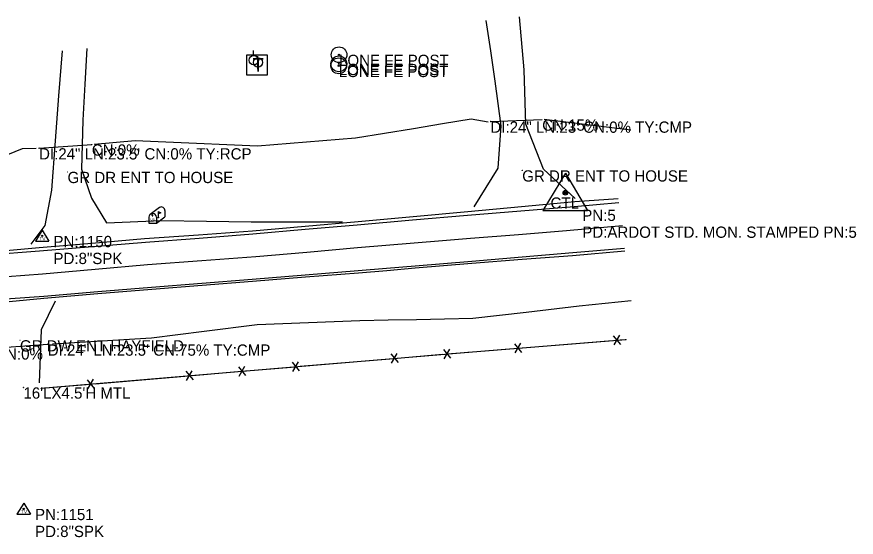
# Model space of a CAD drawing. Extents: x 1138803 to 1169983, y 1655906 to 1658226.
# Drawn here: x 1143123.5 to 1143496, y 1657549.2 to 1657780.1 of the extents above; entities that cross this region are included whole.
import ezdxf

# ---------------------------------------------------------------- set-up
doc = ezdxf.new("R2010")
doc.units = 0
for name, color, linetype in [('S_DITCHLINE', 7, 'Continuous'), ('S_DRG_PT_SYM', 7, 'Continuous'), ('S_EDGE_PAVEMENT', 7, 'Continuous'), ('S_FENCE', 7, 'Continuous'), ('S_FENCE_ANNOT', 7, 'Continuous'), ('S_GATE_ANNOT', 7, 'Continuous'), ('S_GRAVEL_ROAD', 7, 'Continuous'), ('S_MAILBOX', 7, 'Continuous'), ('S_MSC_PT_SYM', 7, 'Continuous'), ('S_PAVEMENT_CROWN', 7, 'Continuous'), ('S_PRIMARY_CTL', 7, 'Continuous'), ('S_PRIMARY_CTL_ANNOT', 7, 'Continuous'), ('S_SECONDARY_CTL', 7, 'Continuous'), ('S_SECONDARY_CTL_ANNOT', 7, 'Continuous'), ('S_SHOULDER', 7, 'Continuous'), ('S_SIDE_DRAIN', 7, 'Continuous'), ('S_SIDE_DRAIN_ANNOT', 7, 'Continuous'), ('S_SURVEY_TEXT_ANNOT', 7, 'Continuous'), ('S_TELEPHONE_UTILITIES', 7, 'Continuous'), ('S_UTILITY_POLE', 7, 'Continuous')]:
    doc.layers.add(name, color=color, linetype=linetype)

msp = doc.modelspace()

# ---------------------------------------------------------------- linework, layer by layer
at = {"layer": 'S_DITCHLINE'}
for points in [[(1143157.9, 1657723.55), (1143176.04, 1657725.23), (1143189.62, 1657724.66), (1143203.21, 1657724.08), (1143216.8, 1657723.51), (1143230.38, 1657722.94), (1143252.13, 1657724.66), (1143273.89, 1657726.38), (1143286.72, 1657728.49), (1143299.54, 1657730.6), (1143312.37, 1657732.71), (1143325.2, 1657734.83), (1143332.69, 1657733.58)], [(1143357.57, 1657734.69), (1143376.81, 1657732.34), (1143396.04, 1657729.98)], [(1143030.92, 1657704.21), (1143033.86, 1657704.13), (1143046.72, 1657704.38), (1143059.59, 1657704.63), (1143072.45, 1657704.89), (1143085.32, 1657705.14), (1143105.7, 1657713.44), (1143126.07, 1657721.75), (1143132.06, 1657721.81)], [(1143139.38, 1657634.98), (1143161.32, 1657636.36), (1143183.27, 1657637.73), (1143206.7, 1657640.67), (1143230.12, 1657643.61), (1143252.97, 1657644.48), (1143275.81, 1657645.34), (1143288.34, 1657645.6), (1143300.87, 1657645.86), (1143313.4, 1657646.12), (1143325.93, 1657646.38), (1143349.53, 1657649.14), (1143373.13, 1657651.91), (1143396.24, 1657654.27)]]:
    msp.add_lwpolyline(points, dxfattribs=at)
at = {"layer": 'S_DRG_PT_SYM'}
for points in [[(1143333.7, 1657733.67), (1143333.7, 1657733.72), (1143333.7, 1657733.67), (1143333.65, 1657733.67), (1143333.7, 1657733.67), (1143333.7, 1657733.62), (1143333.7, 1657733.67), (1143333.75, 1657733.67)], [(1143356.69, 1657734.58), (1143356.69, 1657734.63), (1143356.69, 1657734.58), (1143356.64, 1657734.58), (1143356.69, 1657734.58), (1143356.69, 1657734.53), (1143356.69, 1657734.58), (1143356.74, 1657734.58)], [(1143156.81, 1657723.52), (1143156.81, 1657723.57), (1143156.81, 1657723.52), (1143156.76, 1657723.52), (1143156.81, 1657723.52), (1143156.81, 1657723.47), (1143156.81, 1657723.52), (1143156.86, 1657723.52)], [(1143133.4, 1657721.81), (1143133.4, 1657721.86), (1143133.4, 1657721.81), (1143133.35, 1657721.81), (1143133.4, 1657721.81), (1143133.4, 1657721.76), (1143133.4, 1657721.81), (1143133.45, 1657721.81)], [(1143137.25, 1657634.81), (1143137.25, 1657634.86), (1143137.25, 1657634.81), (1143137.2, 1657634.81), (1143137.25, 1657634.81), (1143137.25, 1657634.76), (1143137.25, 1657634.81), (1143137.3, 1657634.81)], [(1143137.27, 1657634.75), (1143137.27, 1657634.8), (1143137.27, 1657634.75), (1143137.22, 1657634.75), (1143137.27, 1657634.75), (1143137.27, 1657634.7), (1143137.27, 1657634.75), (1143137.32, 1657634.75)]]:
    msp.add_lwpolyline(points, dxfattribs=at)
at = {"layer": 'S_EDGE_PAVEMENT'}
for points in [[(1143390.63, 1657697.57), (1143370.83, 1657695.87), (1143347.2, 1657693.91), (1143323.57, 1657691.95), (1143299.08, 1657689.83), (1143274.59, 1657687.71), (1143251.45, 1657685.73), (1143228.31, 1657683.74), (1143204.47, 1657681.83), (1143180.63, 1657679.91), (1143157.13, 1657678.05), (1143133.64, 1657676.19), (1143110.57, 1657674.3)], [(1143393.24, 1657677.32), (1143370.23, 1657675.37), (1143347.86, 1657673.46), (1143325.49, 1657671.56), (1143312.87, 1657670.53), (1143300.25, 1657669.51), (1143287.63, 1657668.48), (1143275.01, 1657667.46), (1143251.51, 1657665.49), (1143228.01, 1657663.53), (1143205.65, 1657661.77), (1143183.29, 1657660), (1143159.42, 1657658.05), (1143135.55, 1657656.09), (1143112.14, 1657654.33)]]:
    msp.add_lwpolyline(points, dxfattribs=at)
at = {"layer": 'S_FENCE'}
for p, q in [((1143324.05, 1657631.37), (1143393.86, 1657637)), ((1143388.24, 1657638.6), (1143391.43, 1657634.75)), ((1143388.24, 1657638.6), (1143391.43, 1657634.75)), ((1143388.57, 1657634.52), (1143391.1, 1657638.83)), ((1143388.57, 1657634.52), (1143391.1, 1657638.83)), ((1143344.38, 1657635.06), (1143347.57, 1657631.21)), ((1143344.38, 1657635.06), (1143347.57, 1657631.21)), ((1143344.71, 1657630.98), (1143347.24, 1657635.29)), ((1143344.71, 1657630.98), (1143347.24, 1657635.29)), ((1143225.34, 1657623.07), (1143324.05, 1657631.37)), ((1143289.51, 1657630.52), (1143292.71, 1657626.68)), ((1143289.51, 1657630.52), (1143292.71, 1657626.68)), ((1143289.85, 1657626.44), (1143292.36, 1657630.76)), ((1143289.85, 1657626.44), (1143292.36, 1657630.76)), ((1143312.86, 1657632.48), (1143316.06, 1657628.64)), ((1143312.86, 1657632.48), (1143316.06, 1657628.64)), ((1143313.2, 1657628.4), (1143315.71, 1657632.72)), ((1143313.2, 1657628.4), (1143315.71, 1657632.72)), ((1143245.66, 1657626.83), (1143248.86, 1657622.99)), ((1143245.66, 1657626.83), (1143248.86, 1657622.99)), ((1143246, 1657622.75), (1143248.52, 1657627.07)), ((1143246, 1657622.75), (1143248.52, 1657627.07)), ((1143134.37, 1657615.29), (1143225.34, 1657623.07)), ((1143198.52, 1657622.83), (1143201.73, 1657618.99)), ((1143198.52, 1657622.83), (1143201.73, 1657618.99)), ((1143198.87, 1657618.75), (1143201.38, 1657623.08)), ((1143198.87, 1657618.75), (1143201.38, 1657623.08)), ((1143221.87, 1657624.83), (1143225.08, 1657620.99)), ((1143221.87, 1657624.83), (1143225.08, 1657620.99)), ((1143222.22, 1657620.74), (1143224.73, 1657625.07)), ((1143222.22, 1657620.74), (1143224.73, 1657625.07)), ((1143154.68, 1657619.09), (1143157.89, 1657615.25)), ((1143154.68, 1657619.09), (1143157.89, 1657615.25)), ((1143155.03, 1657615), (1143157.54, 1657619.33)), ((1143155.03, 1657615), (1143157.54, 1657619.33))]:
    msp.add_line(p, q, dxfattribs=at)
for points in [[(1143391.26, 1657636.79), (1143393.86, 1657637)], [(1143391.26, 1657636.79), (1143393.86, 1657637)], [(1143347.97, 1657633.3), (1143387.84, 1657636.51)], [(1143347.97, 1657633.3), (1143387.84, 1657636.51)], [(1143292.54, 1657628.72), (1143312.46, 1657630.4)], [(1143292.54, 1657628.72), (1143312.46, 1657630.4)], [(1143316.45, 1657630.73), (1143324.05, 1657631.37)], [(1143316.45, 1657630.73), (1143324.05, 1657631.37)], [(1143324.05, 1657631.37), (1143343.98, 1657632.98)], [(1143324.05, 1657631.37), (1143343.98, 1657632.98)], [(1143249.25, 1657625.08), (1143289.11, 1657628.43)], [(1143249.25, 1657625.08), (1143289.11, 1657628.43)], [(1143201.56, 1657621.03), (1143221.48, 1657622.74)], [(1143201.56, 1657621.03), (1143221.48, 1657622.74)], [(1143225.34, 1657623.07), (1143245.27, 1657624.74)], [(1143225.34, 1657623.07), (1143245.27, 1657624.74)], [(1143158.28, 1657617.34), (1143198.13, 1657620.74)], [(1143158.28, 1657617.34), (1143198.13, 1657620.74)], [(1143134.37, 1657615.29), (1143154.29, 1657617)], [(1143134.37, 1657615.29), (1143154.29, 1657617)]]:
    msp.add_lwpolyline(points, dxfattribs=at)
for centre, radius in [((1143266.53, 1657763.29), 3.49), ((1143266.53, 1657763.29), 0.247), ((1143266.38, 1657758.37), 3.49), ((1143266.43, 1657759.26), 3.49), ((1143266.53, 1657763.29), 0.0349), ((1143266.38, 1657758.37), 0.247), ((1143266.43, 1657759.26), 0.247), ((1143266.38, 1657758.37), 0.0349), ((1143266.43, 1657759.26), 0.0349)]:
    msp.add_circle(centre, radius, dxfattribs=at)
at = {"layer": 'S_GRAVEL_ROAD'}
for points in [[(1143331.67, 1657778.48), (1143333.68, 1657765), (1143335.7, 1657751.52), (1143338.37, 1657731.76), (1143337.03, 1657712.89), (1143326.31, 1657695.78)], [(1143371.29, 1657699.48), (1143357.22, 1657712.56), (1143349.36, 1657732.42), (1143348.65, 1657756.65), (1143346.63, 1657780.13)], [(1143129.86, 1657679.3), (1143136.12, 1657687.51), (1143139.05, 1657703.19), (1143140.75, 1657725.1), (1143142.24, 1657745.04), (1143143.73, 1657764.98)], [(1143154.53, 1657766.13), (1143153.68, 1657750.21), (1143152.83, 1657734.29), (1143152.2, 1657712.49), (1143156.72, 1657699.62), (1143163.33, 1657688.73), (1143187.71, 1657689.74), (1143207.64, 1657689.47), (1143227.57, 1657689.19), (1143247.78, 1657689.17), (1143267.99, 1657689.14)], [(1143140.58, 1657654.02), (1143134.3, 1657641.28), (1143133.48, 1657617.76)]]:
    msp.add_lwpolyline(points, dxfattribs=at)
at = {"layer": 'S_MAILBOX'}
for p, q in [((1143182.69, 1657692.48), (1143186.82, 1657695.59)), ((1143186.3, 1657693.77), (1143186.3, 1657691.05)), ((1143189.25, 1657694.11), (1143189.25, 1657691.4)), ((1143182.13, 1657691.2), (1143182.13, 1657688.49)), ((1143185.46, 1657688.49), (1143189.25, 1657691.4)), ((1143185.46, 1657691.2), (1143185.46, 1657688.49)), ((1143182.13, 1657688.49), (1143185.46, 1657688.49))]:
    msp.add_line(p, q, dxfattribs=at)
for points in [[(1143186.3, 1657693.77), (1143187.41, 1657693.1), (1143186.3, 1657692.75)], [(1143183.32, 1657692.32), (1143183.54, 1657692.18), (1143183.54, 1657691.79), (1143183.84, 1657691.79), (1143183.84, 1657692.15), (1143183.65, 1657692.4), (1143183.32, 1657692.35)]]:
    msp.add_lwpolyline(points, dxfattribs=at)
for centre, end in [((1143183.79, 1657691.2), 180), ((1143187.59, 1657694.11), 117.5718)]:
    msp.add_arc(centre, 1.66, 0, end, dxfattribs=at)
msp.add_ellipse((1143186.3, 1657691.05), major_axis=(0.145, 0.132), ratio=0.564646, dxfattribs=at)
at = {"layer": 'S_MSC_PT_SYM'}
for points in [[(1143146.05, 1657711.34), (1143146.05, 1657711.39), (1143146.05, 1657711.34), (1143146, 1657711.34), (1143146.05, 1657711.34), (1143146.05, 1657711.29), (1143146.05, 1657711.34), (1143146.1, 1657711.34)], [(1143347.82, 1657712.01), (1143347.82, 1657712.06), (1143347.82, 1657712.01), (1143347.77, 1657712.01), (1143347.82, 1657712.01), (1143347.82, 1657711.96), (1143347.82, 1657712.01), (1143347.87, 1657712.01)], [(1143393.86, 1657637), (1143393.86, 1657637.05), (1143393.86, 1657637), (1143393.81, 1657637), (1143393.86, 1657637), (1143393.86, 1657636.95), (1143393.86, 1657637), (1143393.91, 1657637)], [(1143124.91, 1657636.63), (1143124.91, 1657636.68), (1143124.91, 1657636.63), (1143124.86, 1657636.63), (1143124.91, 1657636.63), (1143124.91, 1657636.58), (1143124.91, 1657636.63), (1143124.96, 1657636.63)], [(1143324.05, 1657631.37), (1143324.05, 1657631.42), (1143324.05, 1657631.37), (1143324, 1657631.37), (1143324.05, 1657631.37), (1143324.05, 1657631.32), (1143324.05, 1657631.37), (1143324.1, 1657631.37)], [(1143225.34, 1657623.07), (1143225.34, 1657623.12), (1143225.34, 1657623.07), (1143225.29, 1657623.07), (1143225.34, 1657623.07), (1143225.34, 1657623.02), (1143225.34, 1657623.07), (1143225.39, 1657623.07)], [(1143126.46, 1657615.69), (1143126.46, 1657615.74), (1143126.46, 1657615.69), (1143126.41, 1657615.69), (1143126.46, 1657615.69), (1143126.46, 1657615.64), (1143126.46, 1657615.69), (1143126.51, 1657615.69)], [(1143134.37, 1657615.29), (1143134.37, 1657615.34), (1143134.37, 1657615.29), (1143134.32, 1657615.29), (1143134.37, 1657615.29), (1143134.37, 1657615.24), (1143134.37, 1657615.29), (1143134.42, 1657615.29)]]:
    msp.add_lwpolyline(points, dxfattribs=at)
at = {"layer": 'S_PAVEMENT_CROWN'}
msp.add_lwpolyline([(1143392.35, 1657687.36), (1143367.54, 1657685.17), (1143346.23, 1657683.44), (1143324.92, 1657681.71), (1143312.39, 1657680.68), (1143299.85, 1657679.65), (1143287.32, 1657678.62), (1143274.79, 1657677.59), (1143252.19, 1657675.6), (1143229.6, 1657673.61), (1143205.6, 1657671.86), (1143181.59, 1657670.1), (1143158.27, 1657668.03), (1143134.96, 1657665.96), (1143111.19, 1657664.11)], dxfattribs=at)
at = {"layer": 'S_PRIMARY_CTL'}
for p, q in [((1143366.97, 1657710.76), (1143356.94, 1657694.25)), ((1143366.97, 1657710.76), (1143376.8, 1657694.25)), ((1143356.94, 1657694.25), (1143376.8, 1657694.25))]:
    msp.add_line(p, q, dxfattribs=at)
for radius in [1.04, 0.609, 0.344]:
    msp.add_circle((1143366.97, 1657702.06), radius, dxfattribs=at)
at = {"layer": 'S_SECONDARY_CTL'}
for p, q in [((1143134.78, 1657685.52), (1143131.77, 1657680.56)), ((1143134.78, 1657685.52), (1143137.73, 1657680.56)), ((1143131.77, 1657680.56), (1143137.73, 1657680.56)), ((1143126.62, 1657564.4), (1143123.61, 1657559.45)), ((1143126.62, 1657564.4), (1143129.57, 1657559.45)), ((1143123.61, 1657559.45), (1143129.57, 1657559.45))]:
    msp.add_line(p, q, dxfattribs=at)
for centre, radius in [((1143134.78, 1657682.91), 0.311), ((1143134.78, 1657682.91), 0.183), ((1143134.78, 1657682.91), 0.103), ((1143126.62, 1657561.79), 0.311), ((1143126.62, 1657561.79), 0.183), ((1143126.62, 1657561.79), 0.103)]:
    msp.add_circle(centre, radius, dxfattribs=at)
at = {"layer": 'S_SHOULDER'}
for points in [[(1143390.39, 1657699.31), (1143371.11, 1657698.04), (1143347.43, 1657695.79), (1143323.75, 1657693.54), (1143299.36, 1657691.32), (1143274.97, 1657689.1), (1143251.56, 1657687.05), (1143228.15, 1657684.99), (1143204.18, 1657683.29), (1143180.22, 1657681.6), (1143156.87, 1657679.57), (1143133.52, 1657677.55), (1143110.56, 1657675.61)], [(1143393.39, 1657676.09), (1143370.19, 1657674.04), (1143347.85, 1657672.37), (1143325.5, 1657670.71), (1143312.91, 1657669.63), (1143300.32, 1657668.56), (1143287.73, 1657667.48), (1143275.14, 1657666.41), (1143251.61, 1657664.53), (1143228.09, 1657662.65), (1143205.79, 1657660.9), (1143183.48, 1657659.14), (1143159.53, 1657657.17), (1143135.58, 1657655.19), (1143112.25, 1657652.94)]]:
    msp.add_lwpolyline(points, dxfattribs=at)
at = {"layer": 'S_SIDE_DRAIN'}
for p, q in [((1143333.7, 1657733.67), (1143356.69, 1657734.58)), ((1143133.4, 1657721.81), (1143156.81, 1657723.52)), ((1143137.27, 1657634.75), (1143113.93, 1657633.03))]:
    msp.add_line(p, q, dxfattribs=at)
at = {"layer": 'S_TELEPHONE_UTILITIES'}
msp.add_lwpolyline([(1143225.63, 1657754.29), (1143225.63, 1657763.29), (1143234.63, 1657763.29), (1143234.63, 1657754.29)], close=True, dxfattribs=at)
at = {"layer": 'S_UTILITY_POLE'}
for p, q in [((1143228.6, 1657763.02), (1143228.6, 1657765.13)), ((1143230.55, 1657756.94), (1143230.55, 1657762.73))]:
    msp.add_line(p, q, dxfattribs=at)
for centre, radius in [((1143228.72, 1657760.88), 2.13), ((1143230.55, 1657759.87), 2.05)]:
    msp.add_circle(centre, radius, dxfattribs=at)

# ---------------------------------------------------------------- texts
at = {"layer": 'S_FENCE_ANNOT'}
for p in [(1143266.53, 1657758.29), (1143266.38, 1657753.37), (1143266.43, 1657754.26)]:
    msp.add_text('LONE FE POST', height=5, dxfattribs=at).set_placement(p)
at = {"layer": 'S_GATE_ANNOT'}
msp.add_text("16'LX4.5'H MTL", height=5, dxfattribs=at).set_placement((1143126.46, 1657610.69))
at = {"layer": 'S_MAILBOX'}
msp.add_text('US', height=0.96, rotation=360, dxfattribs=at).set_placement((1143182.9, 1657689.68))
at = {"layer": 'S_PRIMARY_CTL'}
msp.add_text('CTL', height=5, rotation=360, dxfattribs=at).set_placement((1143360.38, 1657694.99))
at = {"layer": 'S_PRIMARY_CTL_ANNOT'}
for s, p in [('PN:5', (1143374.47, 1657689.56)), ('PD:ARDOT STD. MON. STAMPED PN:5', (1143374.47, 1657682.06))]:
    msp.add_text(s, height=5, dxfattribs=at).set_placement(p)
at = {"layer": 'S_SECONDARY_CTL'}
for p in [(1143133.57, 1657680.9), (1143125.42, 1657559.78)]:
    msp.add_text('TV', height=1.5, rotation=360, dxfattribs=at).set_placement(p)
at = {"layer": 'S_SECONDARY_CTL_ANNOT'}
for s, p in [('PN:1150', (1143139.78, 1657677.91)), ('PD:8"SPK', (1143139.78, 1657670.41)), ('PN:1151', (1143131.62, 1657556.79)), ('PD:8"SPK', (1143131.62, 1657549.29))]:
    msp.add_text(s, height=5, dxfattribs=at).set_placement(p)
at = {"layer": 'S_SIDE_DRAIN_ANNOT'}
for s, p in [('DI:24" LN:23\' CN:0% TY:CMP', (1143333.7, 1657728.67)), ('CN:15%', (1143356.69, 1657729.58)), ('CN:0%', (1143156.81, 1657718.52)), ('DI:24" LN:23.5\' CN:0% TY:RCP', (1143133.4, 1657716.81)), ('CN:0%', (1143113.93, 1657628.03)), ('DI:24" LN:23.5\' CN:75% TY:CMP', (1143137.27, 1657629.75))]:
    msp.add_text(s, height=5, dxfattribs=at).set_placement(p)
at = {"layer": 'S_SURVEY_TEXT_ANNOT'}
for s, p in [('GR DR ENT TO HOUSE', (1143146.05, 1657706.34)), ('GR DR ENT TO HOUSE', (1143347.82, 1657707.01)), ('GR DW ENT HAYFIELD', (1143124.91, 1657631.63))]:
    msp.add_text(s, height=5, dxfattribs=at).set_placement(p)
at = {"layer": 'S_TELEPHONE_UTILITIES'}
msp.add_text('T', height=6, rotation=360, dxfattribs=at).set_placement((1143228.19, 1657755.79))

doc.saveas('drawing.dxf')
